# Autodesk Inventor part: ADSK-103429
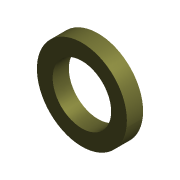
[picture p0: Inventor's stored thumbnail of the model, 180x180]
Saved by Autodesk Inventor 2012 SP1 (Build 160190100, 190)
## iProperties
Shininess: 0.0
Created: 2000-09
Part Number: ADSK-103429
Document SubType Name: Modeling
Stock Number: ADSK-103429
Density: 1 g/cm^3
Material: Default
Density: 0.0
Volumn: 0.0
Area: 0.0
PropertySet Name: Model Information
Control State: 0
Master: False
Checked Out: False
Author: gao
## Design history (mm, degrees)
node "Extrusion1" dims "d2" = 18, "d3" = 0
  sketch "Sketch1"
    geometry: C1 r 32.5 at (-0.143, -1.003); C2 r 50 at (-0.143, -1.003)
    constraints: 2 centre point, 1 coincident
    dimensions: "d0" = 65 diameter of C1; "d1" = 100 diameter of C2
body "Solid1"
